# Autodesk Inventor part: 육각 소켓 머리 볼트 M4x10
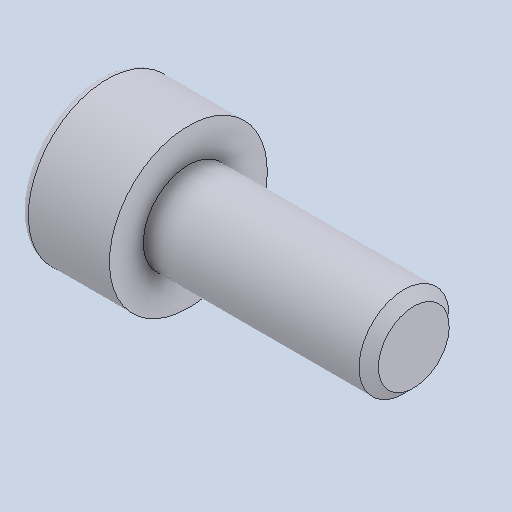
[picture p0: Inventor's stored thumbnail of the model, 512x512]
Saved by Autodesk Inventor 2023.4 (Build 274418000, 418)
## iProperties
Created: 2024-04
Part Number: 육각 소켓 머리 볼트 M4x10
Material: 강철, 연강
Description: 6각머리 태핑 나사
Document SubType Name: Modeling
Designer: EDU
Density: 7.86 g/cm^3
Appearance: 기본값
Author: jhkim
Sending System: Autodesk Inventor 2025
Preprocessor: ST-DEVELOPER v20
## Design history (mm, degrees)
node "육각 소켓 머리 볼트 M4x101"
node "솔리드1"
body "Solid1"
